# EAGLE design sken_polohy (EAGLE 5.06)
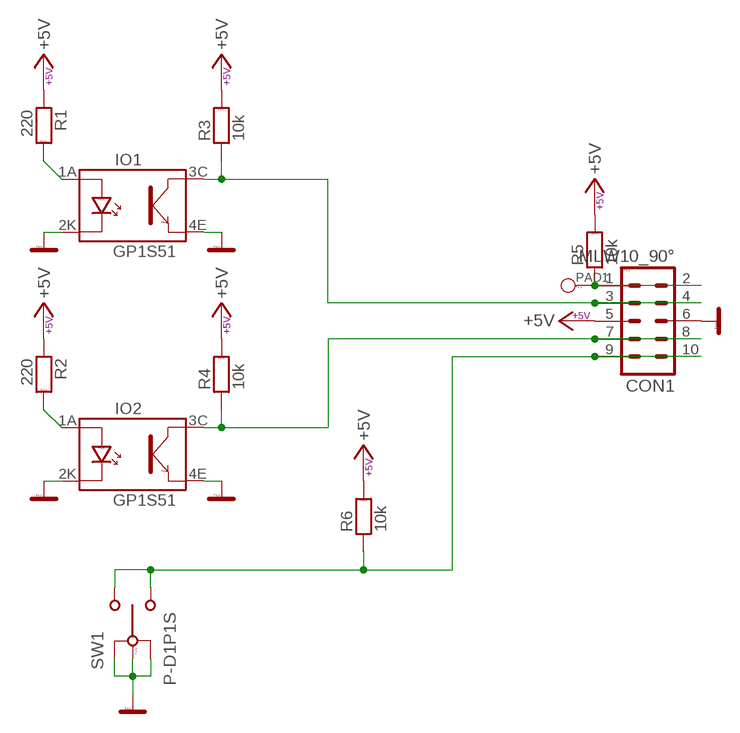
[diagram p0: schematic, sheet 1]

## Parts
CON1  MLW10_90°  [MLW10A]
IO1  GP1S51  [GP1S51]
IO2  GP1S51  [GP1S51]
PAD1  PAD_1  [PAD_1]
R1  220  R_SMD_1206  [1206]
R2  220  R_SMD_1206  [1206]
R3  10k  R_SMD_1206  [1206]
R4  10k  R_SMD_1206  [1206]
R5  10k  R_SMD_1206  [1206]
R6  10k  R_SMD_1206  [1206]
SW1  P-D1P1S  [P-D1P1S]

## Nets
+5V: CON1.5 R1.1 R2.1 R3.2 R4.2 R5.2 R6.2
GND: CON1.6 IO1.2K(K) IO1.4E(E) IO2.2K(K) IO2.4E(E) SW1.2 SW1.3 SW1.4
N$1: CON1.3 CON1.4 IO1.3C(C) R3.1
N$2: IO1.1A(A) R1.2
N$3: IO2.1A(A) R2.2
N$4: CON1.1 CON1.2 PAD1.1 R5.1
N$7: CON1.7 CON1.8 IO2.3C(C) R4.1
N$10: CON1.9 CON1.10 R6.1 SW1.1 SW1.5

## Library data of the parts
CON1 = #PaJa_konektory:MLW10: Konektory MLW - vidlice - 10x
IO1 IO2 = #PaJa_31:GP1S51: OPTOzavora - GP1S51
PAD1 = #PaJa_31:PAD_1: Pajeci bod - 2,54 mm prumer
R1-R6 = #PaJa_31:R: Rezistor
SW1 = #PaJa_prepinace:P-D1P1S: Mikrospinac packovy - 100mA, pouzivany v CD/DVD mechanikach

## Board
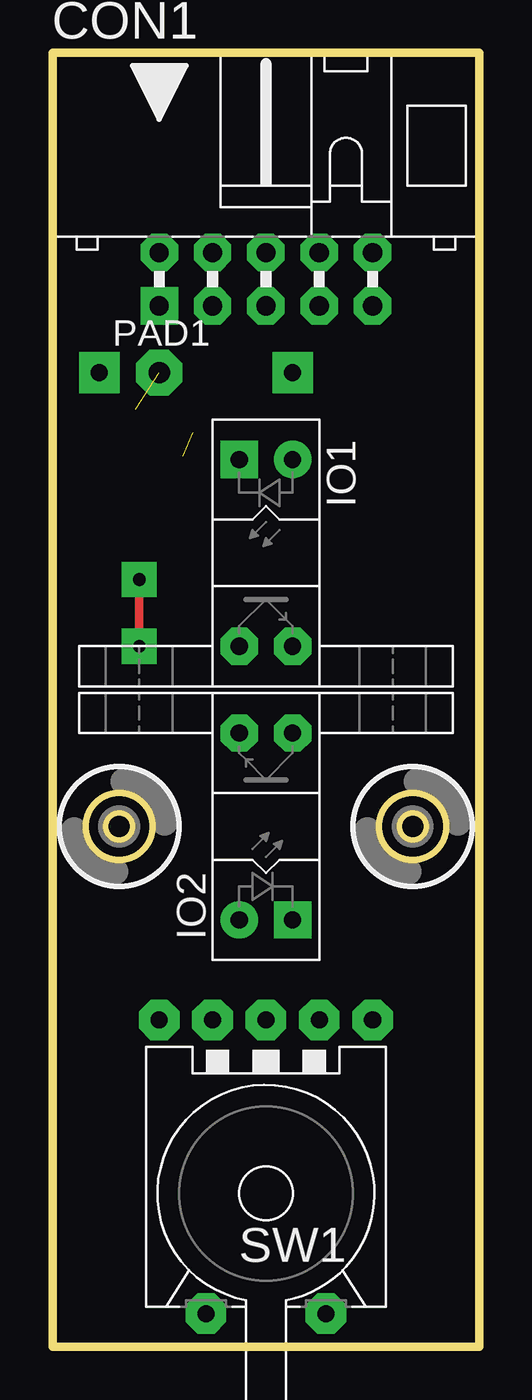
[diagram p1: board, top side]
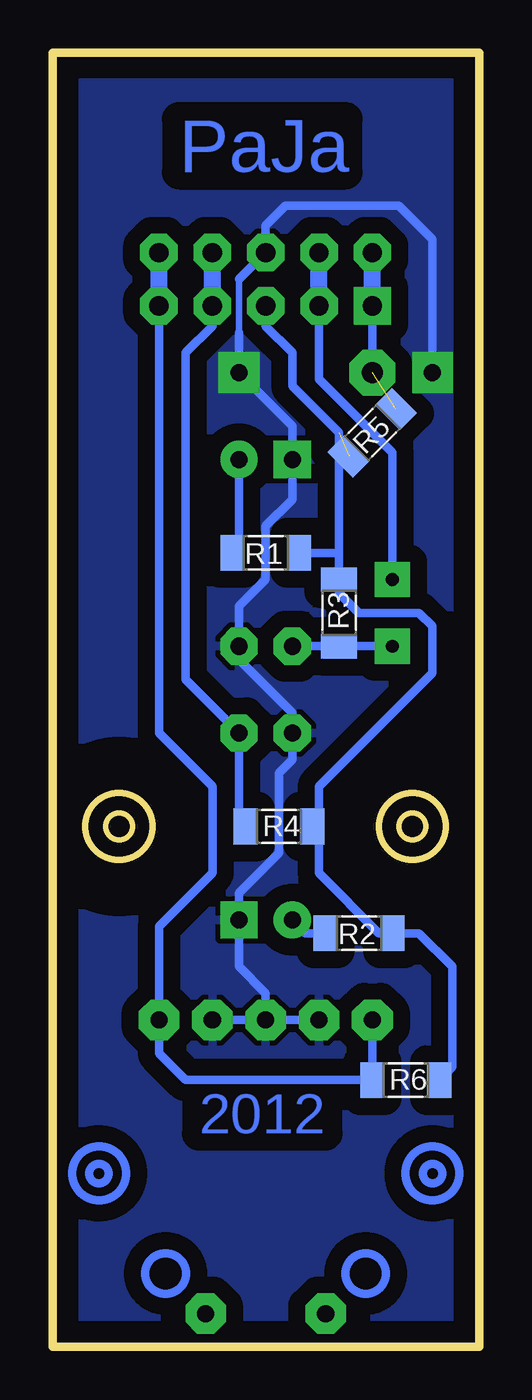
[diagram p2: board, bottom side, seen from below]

Size 20.31 x 61.59 mm. Coordinates in mm from the lower left corner, seen from the top.
Outline: 0,0 20.31,0 20.31,61.59 0,61.59 0,0
Copper layers (1*16): Top 0.035mm / dielectric 1.5mm / Bottom 0.035mm
Design rules "default": minimum track width 10mil, minimum drill 24mil, track to track 8mil, track to pad 8mil, pad to pad 8mil, via to via 8mil, smd to smd 8mil, copper to edge 40mil, drill to drill 8mil, minimum pad ring 10mil, minimum via ring 8mil, stop-mask expansion 4mil, vias tented up to drill 0mil, thermal gap 10mil

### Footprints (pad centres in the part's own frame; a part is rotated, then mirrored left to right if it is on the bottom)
MLW10A = drill 0.914 pad 1.778 square: 1 -5.08,-1.27 | drill 0.914 pad 1.778 octagon: 2 -5.08,1.27; 3 -2.54,-1.27; 4 -2.54,1.27; 5 0,-1.27; 6 0,1.27; 7 2.54,-1.27; 8 2.54,1.27; 9 5.08,-1.27; 10 5.08,1.27
GP1S51 = drill 0.813 pad 1.778 round: 1A -4.445,1.27 | drill 0.813 pad 1.778 square: 2K -4.445,-1.27 | drill 0.813 pad 1.778 octagon: 3C 4.445,-1.27; 4E 4.445,1.27
PAD_1 = drill 1.016 pad 2.184 octagon: 1 0,0
1206 = smd 1.143 x 1.702: 1 -1.587,0; 2 1.587,0
P-D1P1S = drill 0.813 pad 1.93 octagon: 1 5.08,0; 1.1 2.857,13.97; 2 2.54,0; 3 0,0; 4 -2.54,0; 5 -5.08,0; 5.1 -2.857,13.97
HOLE_3,0 = hole 3.2: 0,0

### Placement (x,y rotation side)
CON1  10.16,50.8 0 top
IO1  10.16,37.78 270 top
IO2  10.16,24.77 90 top
PAD1  5.08,46.35 0 top
R1  10.16,37.78 180 bottom
R2  5.71,19.68 180 bottom
R3  6.67,34.92 90 bottom
R4  9.53,24.77 0 bottom
R5  5.08,43.5 225 bottom
R6  3.49,12.7 0 bottom
SW1  10.16,15.56 180 top
U$1  [HOLE_3,0]  3.17,24.77 0 top
U$5  [HOLE_3,0]  17.14,24.77 0 top

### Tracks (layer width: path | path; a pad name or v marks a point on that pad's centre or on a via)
+5V  (1 unrouted)
  Bottom 0.406: 6.67,37.78 R3.2 6.67,35.88 5.71,34.92 2.86,34.92 2.22,34.29 2.22,32.07 7.62,26.67 7.62,24.77 | R2.1 4.76,19.68 7.62,22.54 7.62,24.77 | 7.62,24.77 R4.2 | 6.67,37.78 R1.1 | 6.67,37.78 6.67,43.5 8.89,45.72 8.89,47.31 10.16,48.58 CON1.5 | R2.1 4.13,19.37 | R2.1 2.86,19.68 1.27,18.1 1.27,13.34 R6.2
GND  (via drill 0.81 pad 1.93)
  Bottom 0.305: 11.43,48.26 11.43,50.8
  Bottom 0.406: SW1.2 SW1.3 | SW1.3 SW1.4 | SW1.3 10.16,16.83 11.43,18.1 IO2.2K 11.43,21.59 9.53,23.5 9.53,27.3 8.89,27.94 IO2.4E 8.89,30.16 11.43,32.7 IO1.4E 11.43,35.24 10.16,36.51 10.16,39.05 8.89,40.32 IO1.2K 8.89,43.81 v11.43,46.35 11.43,48.26 | 11.43,50.8 CON1.6 10.16,53.34 9.21,54.29 3.81,54.29 2.22,52.7 v2.22,46.35
  pour Bottom (isolate 0.813): 0,0 20.32,0 20.32,61.59 0,61.59
N$1  (via drill 0.6 pad 1.68)
  Top 0.406: v4.13,33.34 v4.13,36.51
  Bottom 0.406: IO1.3C R3.1 v4.13,33.34 | CON1.3 7.62,46.04 4.13,42.55 v4.13,36.51
  Bottom 0.813: CON1.3 CON1.4
N$2
  Bottom 0.406: IO1.1A 11.43,38.1 R1.2
N$3
  Bottom 0.406: R2.2 8.26,19.68 IO2.1A
N$4  (1 unrouted)
  Bottom 0.406: PAD1.1 CON1.1
  Bottom 0.813: CON1.1 CON1.2
N$7
  Bottom 0.406: R4.1 11.43,24.77 IO2.3C 13.97,31.75 13.97,47.31 12.7,48.58 CON1.7
  Bottom 0.813: CON1.7 CON1.8
N$10
  Bottom 0.406: SW1.1 R6.1 13.97,12.7 15.24,13.97 SW1.5 15.24,20 12.7,22.54 12.7,26.67 15.24,29.21 CON1.9
  Bottom 0.813: CON1.9 CON1.10
(copper drawn outside any net)
  shapes: Bottom circle x6

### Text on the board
Bottom: PaJa | 2012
